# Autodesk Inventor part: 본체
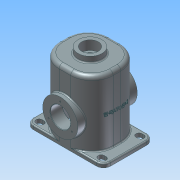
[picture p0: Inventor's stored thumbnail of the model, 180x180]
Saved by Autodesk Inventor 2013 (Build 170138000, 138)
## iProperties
Company: 한국ATC센터
Created: 2014-10
Part Number: 본체
Document SubType Name: Modeling
Designer: 한국ATC센터
Density: 2.71 g/cm^3
Material: 알루미늄 6061
Mass: 2951.25 g
Surface Area: 2149.45 cm^2
Volume: 1089.02 cm^3
Author: KYOUNG IL JANG
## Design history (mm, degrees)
sketch "스케치1"
  geometry: L1 (-70, 65)-(70, 65); L2 (70, 65)-(70, -65); L3 (70, -65)-(-70, -65); L4 (-70, -65)-(-70, 65); 3 further points
  constraints: 8 end point, 2 midpoint, 2 parallel, 1 horizontal, 1 horizontal alignment, 1 perpendicular, 1 vertical alignment
  dimensions: "d0" = 140 distance of L2.end L3.end; "d68" = 130 distance of L3.end L1.start
extrude "돌출1" new body sketch "스케치1" distance "d1" = 180; taper "d2" = 0 deg
fillet "모깎기1" dims "d3" = 55
feature "쉘1" dims "d4" = 10
sketch "스케치2"
  geometry: L1 (-70, 10)-(-70, -10) reference; L2 (-15, -65)-(-82, -65); L3 (-82, 65)-(-15, 65); L4 (-83, 57)-(-78, 57); L5 (-78, 41)-(-83, 41); L6 (-100, 47)-(-100, -47); A1 r 55 centre (-15, 10) between (-15, 65) and (-70, 10) reference; A2 r 55 centre (-15, -10) between (-70, -10) and (-15, -65) reference; A3 r 8 centre (-78, 49) between (-78, 41) and (-78, 57); A4 r 8 centre (-83, 49) between (-83, 57) and (-83, 41); A5 r 18 centre (-82, 47) between (-82, 65) and (-100, 47); A6 r 18 centre (-82, -47) between (-100, -47) and (-82, -65); 1 further point
  constraints: 10 end point, 9 tangent, 8 point on circle, 4 centre point, 2 parallel, 2 perpendicular, 1 equal radius
  dimensions: "d6" = 49 vertical distance of point (0, 0) A3.centre; "d8" = 16 distance between parallel lines of L4 L5; "d64" = 18 radius of A5; "d65" = 8 distance from line of A3.centre L1; "d66" = 30 distance between parallel lines of L6 L1; "d67" = 5 distance of A4.centre A3.centre
extrude "돌출2" join sketch "스케치2" distance "d9" = 10; taper "d10" = 0 deg
extrude "돌출3" cut sketch "스케치2" stored distance "d11" = 10; taper "d12" = 0 deg
sketch "스케치3"
  geometry: L1 (-65, 10)-(-65, 180) reference; L2 (-55, 0)-(-55, 170) reference; L3 (-77, 75)-(-45, 75); L4 (10, 0)-(-10, 0) reference; L5 (-77, 75)-(-77, 120.5); L6 (-77, 120.5)-(-55, 120.5); L7 (-55, 120.5)-(-45, 110.5); L8 (-45, 110.5)-(-45, 75); 3 further points
  constraints: 10 end point, 4 perpendicular, 1 point on line
  dimensions: "d13" = 75 distance between parallel lines of L3 L4; "d14" = 12 distance from line of L1 L3.start; "d15" = 10 distance from line of L3.end L2; "d16" = 91 diameter of L6 L3; "d17" = 135 deg angle of L7 L2
revolve "회전1" sketch "스케치3" stored, may be unused: angle "d18" = 90 deg
sketch "스케치4"
  geometry: C1 r 45.5 at (0, 0) reference; 2 further points
  constraints: 1 vertical alignment
  dimensions: "d19" = 35 distance of C1.centre point (0, 35)
hole "구멍1" sketch "스케치4" at (0, 35) diameter "d20" = 3.459; stored, may be unused: countersink angle "d24" = 90 deg, drill point angle "d26" = 118 deg; dims "d21" = 13, "d22" = 4, "d23" = 2, "d25" = 16
fillet "모깎기2" dims "d30" = 3
hole "구멍2" diameter "d33" = 52; stored, may be unused: countersink angle "d37" = 90 deg, drill point angle "d39" = 118 deg; dims "d31" = 10, "d32" = 10, "d34" = 13, "d35" = 4, "d36" = 2, "d38" = 16
sketch "스케치5"
  geometry: C1 r 31 at (0, 0); 1 further point
  constraints: 1 centre point, 1 coincident
  dimensions: "d40" = 62 diameter of C1
extrude "돌출4" join sketch "스케치5" distance "d41" = 15; taper "d42" = 0 deg
hole "구멍3" diameter "d45" = 43; stored, may be unused: countersink angle "d49" = 90 deg, drill point angle "d51" = 118 deg; dims "d43" = 10, "d44" = 10, "d46" = 13, "d47" = 4, "d48" = 2, "d50" = 16
fillet "모깎기3" dims "d52" = 3
fillet "모깎기4" dims "d53" = 3
chamfer "모따기1" distance "d55" = 1; stored, may be unused: second distance "d56" = 2, angle "d57" = 45 deg
sketch "스케치6"
  geometry: 2 further points
  constraints: 1 vertical alignment, 1 other
  dimensions: "d71" = 90 distance of point (0, 0) point (0, 90)
feature "엠보싱2" sketch "스케치6" dims "d0" = 140, "d68" = 130, "d72" = 1, "d73" = 0
fillet "모깎기6" dims "d74" = 10
sketch "스케치7"
  geometry: C1 r 15 at (0, 0); C2 r 21.5 at (0, 0) reference; C3 r 25 at (0, 0); 1 further point
  constraints: 2 centre point, 2 coincident
  dimensions: "d61" = 30 diameter of C1; "d75" = 50 diameter of C3
extrude "돌출5" join sketch "스케치7" distance "d62" = 10; taper "d63" = 0 deg
feature "면 이동1" dims "d76" = 1
node "솔리드1"
mirror "대칭1"
mirror "대칭2"
pattern_circular "원형 패턴1" dims angle "d28" = 360 deg
mirror "대칭3"
